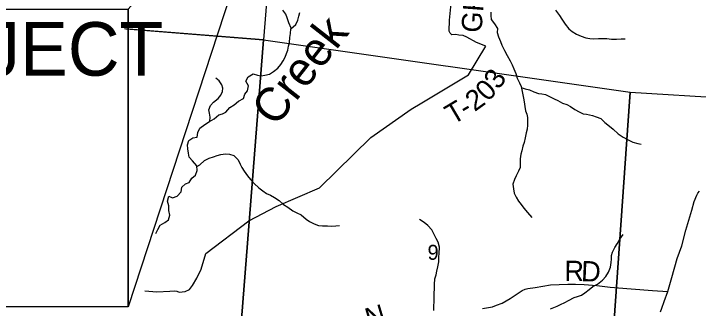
# Model space of a CAD drawing. Extents: x 0 to 40.8, y 0 to 22.
# Drawn here: x 3.599 to 5.517, y 15.397 to 16.222 of the extents above; entities that cross this region are included whole.
import ezdxf

# ---------------------------------------------------------------- set-up
doc = ezdxf.new("R2010")
doc.units = 0
for name, color, linetype in [('Default', 7, 'Continuous'), ('GM_X_County_Road', 7, 'Continuous'), ('GM_X_Minor_River', 7, 'Continuous'), ('GM_X_Minor_River_Text', 7, 'Continuous'), ('GM_X_Section', 7, 'Continuous'), ('GM_X_Section_Text', 7, 'Continuous'), ('GM_X_Township_Road', 7, 'Continuous'), ('GM_X_Township_Road_Text', 7, 'Continuous')]:
    doc.layers.add(name, color=color, linetype=linetype)

msp = doc.modelspace()

# ---------------------------------------------------------------- linework, layer by layer
at = {"layer": 'Default'}
for points in [[(3.9195, 16.2351), (4.3506, 16.715), (3.9199, 15.4019)], [(2.3843, 16.2351), (3.9199, 16.2351), (3.9199, 15.4019), (2.3843, 15.4019)]]:
    msp.add_lwpolyline(points, close=True, dxfattribs=at)
at = {"layer": 'GM_X_County_Road'}
msp.add_lwpolyline([(5.4108, 15.3879), (5.4148, 15.3982), (5.4214, 15.4165), (5.4315, 15.4444), (5.4423, 15.4839), (5.458, 15.5368), (5.4703, 15.572), (5.482, 15.6164), (5.4983, 15.6723), (5.5055, 15.6962), (5.5123, 15.7139), (5.5156, 15.7199), (5.5205, 15.725)], dxfattribs=at)
at = {"layer": 'GM_X_Minor_River'}
for points in [[(3.9972, 15.6067), (4.0025, 15.6181), (4.0093, 15.6298), (4.0229, 15.6378), (4.0328, 15.645), (4.0366, 15.6579), (4.0335, 15.6715), (4.0335, 15.6841), (4.0297, 15.697), (4.0339, 15.7117), (4.0441, 15.7068), (4.057, 15.711), (4.068, 15.7231), (4.0699, 15.7368), (4.0805, 15.7459), (4.0908, 15.7497), (4.098, 15.7618), (4.1086, 15.7705), (4.1127, 15.7834), (4.1124, 15.796), (4.1002, 15.8104), (4.0911, 15.8206), (4.0885, 15.832), (4.087, 15.8441), (4.0862, 15.8555), (4.0896, 15.8669), (4.101, 15.8749), (4.1128, 15.8768), (4.115, 15.8893), (4.1207, 15.9018), (4.1344, 15.9116), (4.1476, 15.9207), (4.1605, 15.928), (4.1738, 15.939), (4.1836, 15.9416), (4.1938, 15.9469), (4.2048, 15.9594), (4.217, 15.9674), (4.2291, 15.9776), (4.2427, 15.9845), (4.2469, 15.9966), (4.2545, 16.0065), (4.2564, 16.0201), (4.2492, 16.0334), (4.256, 16.0455), (4.27, 16.0543), (4.2825, 16.0501), (4.2927, 16.0486), (4.303, 16.0497), (4.3159, 16.0531), (4.3272, 16.0603), (4.339, 16.0698), (4.3477, 16.0797), (4.3537, 16.0903), (4.3591, 16.1005), (4.3636, 16.1104), (4.3666, 16.1199), (4.3693, 16.1309), (4.3716, 16.1419), (4.3727, 16.1551), (4.3746, 16.1669), (4.375, 16.1802), (4.389, 16.1919), (4.3951, 16.2041), (4.3981, 16.2154), (4.4007, 16.2257)], [(4.3767, 16.1817), (4.3697, 16.1965), (4.3651, 16.2109), (4.361, 16.2211), (4.3526, 16.2325)], [(4.9361, 16.2267), (4.9353, 16.2169), (4.9368, 16.2055), (4.9463, 16.1937), (4.9546, 16.1805), (4.9539, 16.1695), (4.9569, 16.1577), (4.963, 16.1441), (4.9668, 16.1338), (4.9736, 16.1194), (4.9812, 16.105), (4.9895, 16.0906), (4.9952, 16.0792), (5.0005, 16.0678), (5.0054, 16.0545), (5.0099, 16.042), (5.0164, 16.0287), (5.0202, 16.0185), (5.0224, 16.0086), (5.0251, 15.995), (5.0274, 15.9855), (5.0292, 15.9756), (5.0308, 15.962), (5.033, 15.9506), (5.0361, 15.9407), (5.038, 15.9312), (5.038, 15.91), (5.0372, 15.899), (5.0349, 15.8891), (5.0323, 15.8747), (5.0289, 15.8618), (5.0251, 15.8516), (5.0224, 15.8387), (5.0198, 15.8288), (5.0182, 15.8155), (5.0179, 15.8042), (5.0175, 15.7913), (5.0133, 15.781), (5.0065, 15.7685), (5.0016, 15.7583), (4.9974, 15.7446), (4.9993, 15.7321), (5.0008, 15.7199), (5.0065, 15.7082), (5.0133, 15.6976), (5.0205, 15.6877), (5.0281, 15.6782), (5.0383, 15.6657), (5.0504, 15.652)], [(5.1164, 16.2324), (5.1282, 16.2172), (5.1342, 16.207), (5.1441, 16.1926), (5.1539, 16.1801), (5.1634, 16.1721), (5.1755, 16.1653), (5.1884, 16.1596), (5.202, 16.155), (5.213, 16.1531), (5.224, 16.152), (5.2373, 16.1524), (5.2498, 16.1531), (5.2608, 16.1524), (5.274, 16.1508), (5.288, 16.1505), (5.3009, 16.152), (5.3123, 16.1516)], [(4.1484, 15.9212), (4.1491, 15.9321), (4.1476, 15.9435), (4.1461, 15.9534), (4.1503, 15.9648), (4.159, 15.9742), (4.1719, 15.9845), (4.1798, 15.994), (4.1844, 16.0042), (4.1848, 16.0137), (4.1817, 16.0232), (4.1749, 16.0338), (4.1651, 16.0414)], [(5.0208, 16.0157), (5.0315, 16.0117), (5.044, 16.0094), (5.0558, 16.0033), (5.069, 15.9991), (5.0789, 15.998), (5.0891, 15.9961), (5.1134, 15.984), (5.1232, 15.9794), (5.1368, 15.9714), (5.149, 15.9684), (5.1584, 15.9623), (5.1709, 15.9536), (5.1831, 15.9471), (5.1941, 15.9422), (5.2039, 15.9407), (5.2206, 15.9373), (5.2304, 15.9331), (5.2437, 15.9285), (5.2554, 15.9175), (5.2683, 15.9077), (5.2781, 15.899), (5.2922, 15.8861), (5.3062, 15.8766), (5.3187, 15.8697), (5.3335, 15.8629), (5.3475, 15.8584), (5.3569, 15.8568)], [(4.1124, 15.7948), (4.1203, 15.7994), (4.1336, 15.8111), (4.1468, 15.8179), (4.159, 15.8217), (4.1692, 15.8252), (4.179, 15.8278), (4.1923, 15.8301), (4.2033, 15.8293), (4.2162, 15.8248), (4.2275, 15.813), (4.2336, 15.8009), (4.2385, 15.7914), (4.2446, 15.7811), (4.2544, 15.7682), (4.2624, 15.758), (4.2726, 15.747), (4.2859, 15.7349), (4.2972, 15.7261), (4.3071, 15.7185), (4.3181, 15.714), (4.3298, 15.7075), (4.3427, 15.6992), (4.3552, 15.6882), (4.3669, 15.6802), (4.3813, 15.6703), (4.3923, 15.665), (4.4041, 15.659), (4.4185, 15.6472), (4.4279, 15.6407), (4.4408, 15.6339), (4.4526, 15.6297), (4.4643, 15.6286), (4.4779, 15.6282), (4.4904, 15.6275), (4.5014, 15.6282), (4.5117, 15.6294)], [(4.7757, 15.3914), (4.7757, 15.4036), (4.7765, 15.4161), (4.7772, 15.4279), (4.7768, 15.4408), (4.7776, 15.4514), (4.7776, 15.4639), (4.7791, 15.4802), (4.7821, 15.4916), (4.7844, 15.5015), (4.7875, 15.514), (4.7897, 15.5273), (4.7901, 15.5413), (4.7909, 15.5512), (4.7916, 15.5686), (4.7882, 15.5823), (4.7825, 15.5925), (4.7761, 15.6062), (4.7704, 15.6172), (4.7591, 15.6289), (4.7485, 15.638), (4.7363, 15.6464)], [(5.103, 15.3963), (5.1212, 15.4035), (5.1307, 15.4077), (5.1432, 15.4134), (5.1534, 15.4195), (5.1693, 15.4274), (5.1788, 15.4301), (5.1894, 15.4346), (5.1989, 15.4407), (5.211, 15.4498), (5.2213, 15.4581), (5.2349, 15.465), (5.2489, 15.4763), (5.258, 15.4862), (5.2656, 15.4991), (5.2705, 15.5128), (5.2728, 15.5253), (5.2735, 15.5348), (5.2739, 15.545), (5.2762, 15.5545), (5.2826, 15.5678), (5.2895, 15.5784), (5.2974, 15.5913), (5.3065, 15.6042)]]:
    msp.add_lwpolyline(points, dxfattribs=at)
at = {"layer": 'GM_X_Section'}
for points in [[(3.2542, 16.2539), (3.3398, 17.3372), (3.4517, 17.3312), (4.3898, 17.2759), (4.2989, 16.1489), (3.9097, 16.1796)], [(3.9129, 16.1794), (4.2989, 16.1489), (4.2184, 15.1287), (3.1769, 15.1799), (3.1915, 15.3835)], [(6.3112, 15.6512), (6.2633, 14.9194), (5.2555, 14.9926), (5.3264, 16.0026), (5.5999, 15.9856)]]:
    msp.add_lwpolyline(points, dxfattribs=at)
msp.add_lwpolyline([(5.3264, 16.0026), (5.2555, 14.9926), (4.2184, 15.1287), (4.2989, 16.1489)], close=True, dxfattribs=at)
at = {"layer": 'GM_X_Township_Road'}
for points in [[(4.7567, 15.9814), (4.8734, 16.0508), (4.9218, 16.131), (4.896, 16.1415), (4.8688, 16.1562), (4.8579, 16.1607), (4.846, 16.1623), (4.8378, 16.1635), (4.8263, 16.163), (4.8218, 16.1673), (4.8186, 16.1737), (4.8202, 16.2039), (4.825, 16.2508), (4.8353, 16.4031), (4.8419, 16.5006), (4.8543, 16.6637)], [(3.9663, 15.446), (4, 15.444), (4.0361, 15.4453), (4.0499, 15.446), (4.0562, 15.445), (4.0623, 15.4422), (4.0794, 15.4442), (4.0918, 15.4504), (4.1001, 15.461), (4.1121, 15.4817), (4.1242, 15.5073), (4.1374, 15.5512), (4.2579, 15.6422), (4.3343, 15.6822), (4.4557, 15.7348), (4.5993, 15.8758), (4.7129, 15.9553), (4.7426, 15.973), (4.7567, 15.9814)], [(4.912, 15.3965), (4.9401, 15.4019), (4.9512, 15.4058), (4.967, 15.4122), (4.9898, 15.4253), (5.0232, 15.4473), (5.0318, 15.4508), (5.0396, 15.4526), (5.0596, 15.4559), (5.1027, 15.4629), (5.1512, 15.4646), (5.173, 15.4651), (5.1967, 15.4639), (5.2329, 15.4615), (5.27, 15.4569), (5.3288, 15.4519), (5.3885, 15.4472), (5.4315, 15.4444)]]:
    msp.add_lwpolyline(points, dxfattribs=at)

# ---------------------------------------------------------------- texts
at = {"layer": 'Default'}
msp.add_text('BEGIN PROJECT', height=0.15, dxfattribs=at).set_placement((2.4021, 16.0486))
at = {"layer": 'GM_X_Minor_River_Text'}
msp.add_text('Creek', height=0.09468, rotation=51.9916, dxfattribs=at).set_placement((4.3331, 15.9023))
at = {"layer": 'GM_X_Section_Text'}
msp.add_text('9', height=0.0419, rotation=0, dxfattribs=at).set_placement((4.7584, 15.5333))
at = {"layer": 'GM_X_Township_Road_Text'}
for s, height, rotation, p in [('GRAHAM RD', 0.05682, 85.7054, (4.9093, 16.1675)), ('3', 0.0568, 55.8853, (4.9584, 16.0076)), ('0', 0.0568, 45.7628, (4.9271, 15.974)), ('2', 0.0568, 35.6402, (4.8903, 15.9465)), ('T', 0.0568, 30.5789, (4.8291, 15.91)), ('-', 0.0568, 30.5789, (4.8657, 15.9317)), ('R', 0.0568, 359.6956, (5.1416, 15.4739)), ('D', 0.0568, 357.5003, (5.1877, 15.4737)), ('N', 0.0568, 16.754, (4.5938, 15.3403))]:
    msp.add_text(s, height=height, rotation=rotation, dxfattribs=at).set_placement(p)

doc.saveas('drawing.dxf')
